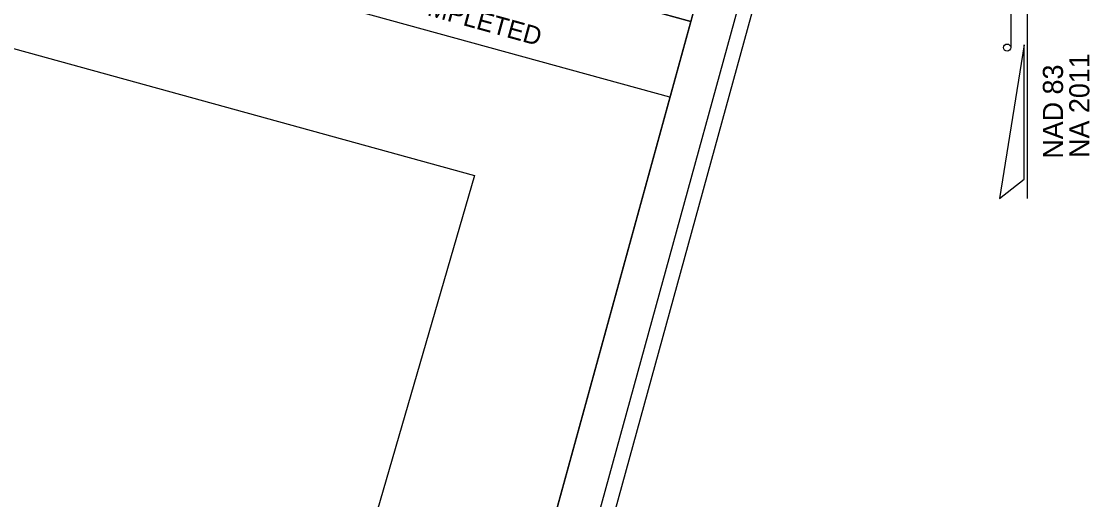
# Model space of a CAD drawing. Extents: x 1641063 to 2864602, y 841295 to 973236.
# Drawn here: x 1642843.9 to 1643162.7, y 842046.5 to 842189.2 of the extents above; entities that cross this region are included whole.
import ezdxf

# ---------------------------------------------------------------- set-up
doc = ezdxf.new("R2010")
doc.units = 0
for name, color, linetype in [('Old_Level_4', 7, 'Continuous'), ('Prop CMT Concrete Structures', 7, 'Continuous'), ('Prop Dimension Text', 7, 'Continuous'), ('Prop DSN Text', 7, 'Continuous'), ('Prop Milling Asph Pvmt at xxxx Depth', 7, 'Continuous'), ('Prop PHM Wetland Impact Area Boundary Line', 7, 'Continuous')]:
    doc.layers.add(name, color=color, linetype=linetype)

msp = doc.modelspace()

# ---------------------------------------------------------------- linework, layer by layer
at = {"layer": 'Old_Level_4'}
msp.add_lwpolyline([(1641192.11, 841741.99), (1642815.27, 841295.31), (1643105.8, 842351.06), (1641482.64, 842797.74)], close=True, dxfattribs=at)
msp.add_lwpolyline([(1641192.11, 841741.99), (1642815.27, 841295.31), (1643105.8, 842351.06), (1641482.64, 842797.74)], close=True, dxfattribs=at)
at = {"layer": 'Prop CMT Concrete Structures'}
for points in [[(1643083.47, 842333.88), (1641637.2, 842731.89), (1641358.6, 841719.52), (1642804.85, 841321.52)], [(1641358.6, 841719.52), (1641637.16, 842731.87), (1642890.57, 842386.98), (1642850.76, 842242.29), (1643043.63, 842189.2), (1642804.85, 841321.52)], [(1642977.06, 842324.21), (1643073.47, 842297.69), (1643043.63, 842189.2), (1642947.21, 842215.73)]]:
    msp.add_lwpolyline(points, close=True, dxfattribs=at)
at = {"layer": 'Prop Dimension Text'}
msp.add_lwpolyline([(1641209.95, 841757.82), (1642816.23, 841315.8), (1643096.16, 842332.97), (1641489.87, 842775.01)], close=True, dxfattribs=at)
at = {"layer": 'Prop DSN Text'}
for p, q in [((1643037.4, 842166.56), (1642844.53, 842219.63)), ((1643037.4, 842166.56), (1642844.53, 842219.63)), ((1643043.63, 842189.2), (1643037.39, 842166.55)), ((1643043.63, 842189.2), (1643037.39, 842166.55))]:
    msp.add_line(p, q, dxfattribs=at)
at = {"layer": 'Prop Milling Asph Pvmt at xxxx Depth'}
for p, q in [((1643144.19, 842136.37), (1643144.19, 842266.37)), ((1643139.15, 842208.55), (1643139.15, 842181.43))]:
    msp.add_line(p, q, dxfattribs=at)
msp.add_lwpolyline([(1643143.13, 842182.17), (1643135.77, 842136.37), (1643143.13, 842142.17)], close=True, dxfattribs=at)
msp.add_circle((1643138.09, 842181.39), 1.06, dxfattribs=at)
at = {"layer": 'Prop PHM Wetland Impact Area Boundary Line'}
msp.add_lwpolyline([(1642834.84, 842332.26), (1642796.64, 842193.46), (1642979.12, 842143.25), (1642931.91, 841980.78), (1642684.68, 842016.94), (1642616.55, 841780.17), (1642867.94, 841712.2), (1642769.91, 841383), (1642620.74, 841424.05), (1642612.78, 841395.12), (1641412.11, 841725.54), (1641476.31, 841958.82), (1641627.07, 841958.82), (1641755.49, 842119.21), (1641752.38, 842181.83), (1641796.56, 842667.29)], dxfattribs=at)

# ---------------------------------------------------------------- texts
at = {"layer": 'Prop DSN Text'}
msp.add_text('UNLESS ALL SIGNATURES COMPLETED', height=5.5, rotation=344.6135, dxfattribs=at).set_placement((1642861.11, 842219.59))
msp.add_text('UNLESS ALL SIGNATURES COMPLETED', height=5.5, rotation=344.6135, dxfattribs=at).set_placement((1642861.11, 842219.59))
at = {"layer": 'Prop Milling Asph Pvmt at xxxx Depth'}
for s, p in [('NA 2011', (1643162.63, 842148.48)), ('NAD 83', (1643154.76, 842148.24))]:
    msp.add_text(s, height=6, rotation=90, dxfattribs=at).set_placement(p)

doc.saveas('drawing.dxf')
